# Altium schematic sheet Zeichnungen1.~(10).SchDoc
size A4; PageSetup: Record=PageOptions¦CenterHorizontal=True¦CenterVertical=True¦PrintScale=1.00¦XCorrection=1.00¦YCorrection=1.00¦PrintKind=0¦BorderSize=5000000¦LeftOffset=0¦BottomOffset=0¦Orientation=2¦PaperLength=1000¦PaperWidth=1000¦Scale=100¦PaperSource=7¦PrintQuality=-3¦MediaType=1¦DitherType=10¦PrintScaleMode=1¦PaperKind=A4¦PaperIndex=9
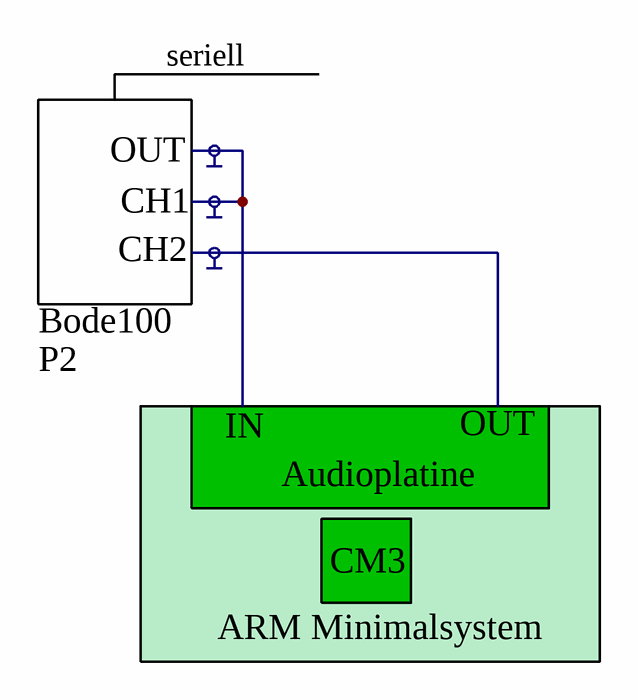
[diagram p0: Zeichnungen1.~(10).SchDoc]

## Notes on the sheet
- OUT
- seriell
- CH2
- CH1
- Bode100
- P2
- IN
- Audioplatine
- ARM Minimalsystem
- CM3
